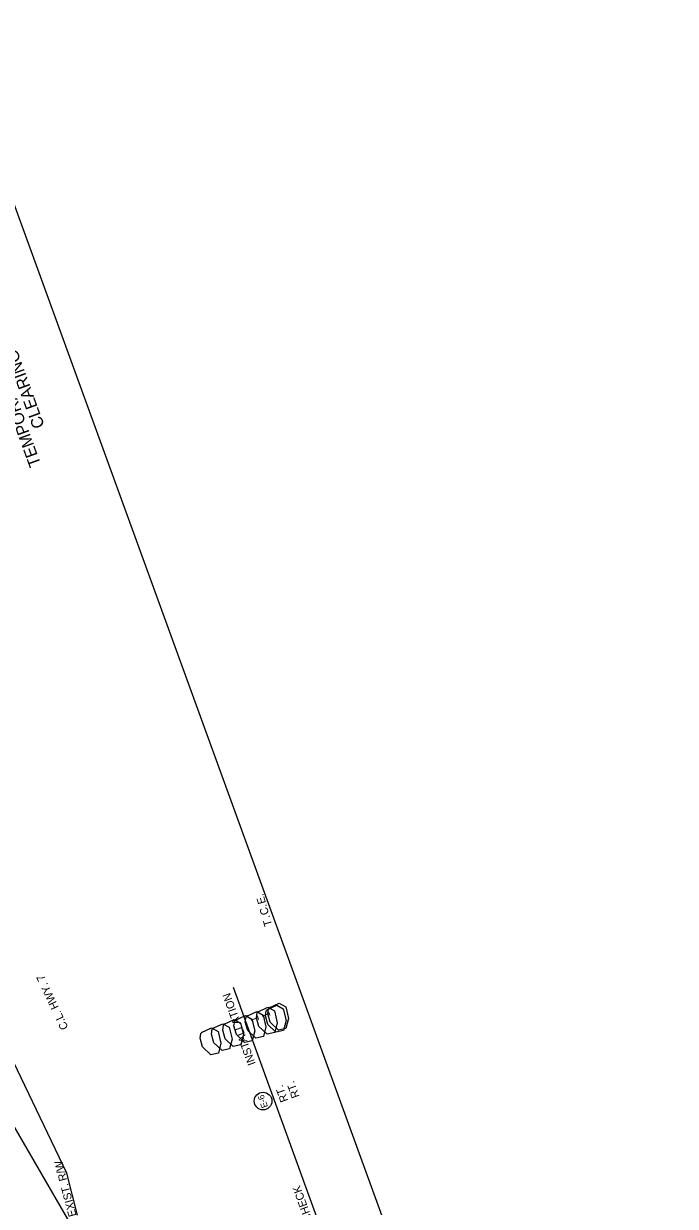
# Model space of a CAD drawing. Extents: x 960650 to 962115, y 1906901 to 1908930.
# Drawn here: x 961626 to 962115, y 1907870 to 1908757 of the extents above; entities that cross this region are included whole.
import ezdxf

# ---------------------------------------------------------------- set-up
doc = ezdxf.new("R2010")
doc.units = 0
for name, color, linetype in [('1', 7, 'Continuous'), ('44', 7, 'Continuous'), ('60', 7, 'Continuous'), ('NO PLOT', 7, 'Continuous'), ('R_Draft', 7, 'Continuous'), ('S_TREE', 7, 'Continuous')]:
    doc.layers.add(name, color=color, linetype=linetype)

msp = doc.modelspace()

# ---------------------------------------------------------------- linework, layer by layer
at = {"layer": '1'}
msp.add_circle((961805.17, 1907948.87), 6.61, dxfattribs=at)
at = {"layer": '44'}
msp.add_line((961865.4, 1907807.44), (961782.97, 1908033.91), dxfattribs=at)
at = {"layer": 'NO PLOT'}
msp.add_lwpolyline([(962114.55, 1907257.7), (961568.91, 1908756.85), (961079.18, 1908578.6), (961182.12, 1908295.76), (961245.55, 1908318.85), (961390.91, 1907919.48), (961327.48, 1907896.39), (961425.36, 1907627.47), (961483.4, 1907648.6), (961600.59, 1907326.6), (961542.56, 1907305.48), (961624.82, 1907079.46)], close=True, dxfattribs=at)
msp.add_lwpolyline([(962114.55, 1907257.7), (961568.91, 1908756.85), (961079.18, 1908578.6), (961182.12, 1908295.76), (961245.55, 1908318.85), (961390.91, 1907919.48), (961327.48, 1907896.39), (961425.36, 1907627.47), (961483.4, 1907648.6), (961600.59, 1907326.6), (961542.56, 1907305.48), (961624.82, 1907079.46)], close=True, dxfattribs=at)
msp.add_lwpolyline([(962114.55, 1907257.7), (961568.91, 1908756.85), (961079.18, 1908578.6), (961182.12, 1908295.76), (961245.55, 1908318.85), (961390.91, 1907919.48), (961327.48, 1907896.39), (961425.36, 1907627.47), (961483.4, 1907648.6), (961600.59, 1907326.6), (961542.56, 1907305.48), (961624.82, 1907079.46)], close=True, dxfattribs=at)
msp.add_lwpolyline([(961666.04, 1907863.2), (961658.05, 1907894.81), (961540.67, 1908139.08), (961533.72, 1908140.56), (961533.72, 1908140.56), (961533.71, 1908140.68), (961532.94, 1908142.63), (961447.22, 1908293.28), (961348.44, 1908423.3), (961301.2, 1908468.29), (961296.15, 1908480.78), (961212.84, 1908631.51), (961200.57, 1908627.76), (961278, 1908455.78), (961347.64, 1908371.59), (961398.93, 1908274.74), (961531.16, 1908140.88), (961533.72, 1908140.56), (961533.72, 1908140.56), (961540.75, 1908123.08), (961535.28, 1908075.65), (961546.11, 1908053.77), (961660.88, 1907856.14)], dxfattribs=at)
at = {"layer": 'S_TREE'}
for points in [[(961801.39, 1908015.72), (961808.86, 1908019.21), (961813.69, 1908016.47), (961815.84, 1908007.64), (961813.9, 1908000.26), (961808.2, 1907998.99), (961802.12, 1908004.87), (961800.26, 1908011.32), (961800.88, 1908014.97), (961802.07, 1908016.2)], [(961801.39, 1908015.72), (961808.86, 1908019.21), (961813.69, 1908016.47), (961815.84, 1908007.64), (961813.9, 1908000.26), (961808.2, 1907998.99), (961802.12, 1908004.87), (961800.26, 1908011.32), (961800.88, 1908014.97), (961802.07, 1908016.2)], [(961808.04, 1908017.22), (961815.51, 1908020.71), (961820.34, 1908017.98), (961822.49, 1908009.15), (961820.55, 1908001.77), (961814.85, 1908000.49), (961808.77, 1908006.38), (961806.91, 1908012.82), (961807.53, 1908016.48), (961808.72, 1908017.7)], [(961809.84, 1908018.8), (961817.32, 1908022.28), (961822.15, 1908019.55), (961824.3, 1908010.72), (961822.36, 1908003.34), (961816.66, 1908002.07), (961810.58, 1908007.95), (961808.72, 1908014.4), (961809.33, 1908018.05), (961810.53, 1908019.27)], [(961776.01, 1908006.48), (961783.49, 1908009.97), (961788.32, 1908007.24), (961790.47, 1907998.41), (961788.53, 1907991.03), (961782.83, 1907989.75), (961776.75, 1907995.64), (961774.89, 1908002.08), (961775.5, 1908005.74), (961776.7, 1908006.96)], [(961776.01, 1908006.48), (961783.49, 1908009.97), (961788.32, 1908007.24), (961790.47, 1907998.41), (961788.53, 1907991.03), (961782.83, 1907989.75), (961776.75, 1907995.64), (961774.89, 1908002.08), (961775.5, 1908005.74), (961776.7, 1908006.96)], [(961776.01, 1908006.48), (961783.49, 1908009.97), (961788.32, 1908007.24), (961790.47, 1907998.41), (961788.53, 1907991.03), (961782.83, 1907989.75), (961776.75, 1907995.64), (961774.89, 1908002.08), (961775.5, 1908005.74), (961776.7, 1908006.96)], [(961776.01, 1908006.48), (961783.49, 1908009.97), (961788.32, 1908007.24), (961790.47, 1907998.41), (961788.53, 1907991.03), (961782.83, 1907989.75), (961776.75, 1907995.64), (961774.89, 1908002.08), (961775.5, 1908005.74), (961776.7, 1908006.96)], [(961776.01, 1908006.48), (961783.49, 1908009.97), (961788.32, 1908007.24), (961790.47, 1907998.41), (961788.53, 1907991.03), (961782.83, 1907989.75), (961776.75, 1907995.64), (961774.89, 1908002.08), (961775.5, 1908005.74), (961776.7, 1908006.96)], [(961784.47, 1908009.56), (961791.95, 1908013.05), (961796.77, 1908010.32), (961798.92, 1908001.49), (961796.99, 1907994.11), (961791.29, 1907992.83), (961785.21, 1907998.72), (961783.35, 1908005.16), (961783.96, 1908008.82), (961785.15, 1908010.04)], [(961784.47, 1908009.56), (961791.95, 1908013.05), (961796.77, 1908010.32), (961798.92, 1908001.49), (961796.99, 1907994.11), (961791.29, 1907992.83), (961785.21, 1907998.72), (961783.35, 1908005.16), (961783.96, 1908008.82), (961785.15, 1908010.04)], [(961784.47, 1908009.56), (961791.95, 1908013.05), (961796.77, 1908010.32), (961798.92, 1908001.49), (961796.99, 1907994.11), (961791.29, 1907992.83), (961785.21, 1907998.72), (961783.35, 1908005.16), (961783.96, 1908008.82), (961785.15, 1908010.04)], [(961784.47, 1908009.56), (961791.95, 1908013.05), (961796.77, 1908010.32), (961798.92, 1908001.49), (961796.99, 1907994.11), (961791.29, 1907992.83), (961785.21, 1907998.72), (961783.35, 1908005.16), (961783.96, 1908008.82), (961785.15, 1908010.04)], [(961784.47, 1908009.56), (961791.95, 1908013.05), (961796.77, 1908010.32), (961798.92, 1908001.49), (961796.99, 1907994.11), (961791.29, 1907992.83), (961785.21, 1907998.72), (961783.35, 1908005.16), (961783.96, 1908008.82), (961785.15, 1908010.04)], [(961792.93, 1908012.64), (961800.4, 1908016.13), (961805.23, 1908013.39), (961807.38, 1908004.57), (961805.45, 1907997.18), (961799.74, 1907995.91), (961793.66, 1908001.8), (961791.81, 1908008.24), (961792.42, 1908011.9), (961793.61, 1908013.12)], [(961759.1, 1908000.33), (961766.57, 1908003.81), (961771.4, 1908001.08), (961773.55, 1907992.25), (961771.62, 1907984.87), (961765.91, 1907983.6), (961759.83, 1907989.48), (961757.98, 1907995.93), (961758.59, 1907999.58), (961759.78, 1908000.8)], [(961767.56, 1908003.41), (961775.03, 1908006.89), (961779.86, 1908004.16), (961782.01, 1907995.33), (961780.07, 1907987.95), (961774.37, 1907986.68), (961768.29, 1907992.56), (961766.43, 1907999.01), (961767.05, 1908002.66), (961768.24, 1908003.88)], [(961767.56, 1908003.41), (961775.03, 1908006.89), (961779.86, 1908004.16), (961782.01, 1907995.33), (961780.07, 1907987.95), (961774.37, 1907986.68), (961768.29, 1907992.56), (961766.43, 1907999.01), (961767.05, 1908002.66), (961768.24, 1908003.88)], [(961767.56, 1908003.41), (961775.03, 1908006.89), (961779.86, 1908004.16), (961782.01, 1907995.33), (961780.07, 1907987.95), (961774.37, 1907986.68), (961768.29, 1907992.56), (961766.43, 1907999.01), (961767.05, 1908002.66), (961768.24, 1908003.88)]]:
    msp.add_lwpolyline(points, dxfattribs=at)

# ---------------------------------------------------------------- texts
at = {"layer": '1'}
msp.add_text('E-6 ', height=4.8, rotation=110, dxfattribs=at).set_placement((961808.91, 1907944.7))
at = {"layer": '44'}
for s, p in [('INSTALLATION', (961799.74, 1907976.85)), ('1', (961802.5, 1908009.3)), ('1', (961810.96, 1908012.38)), ('RT.', (961824.18, 1907949.26)), ('RT.', (961832.64, 1907952.34)), ('ROCK DITCH CHECK', (961860.23, 1907810.66))]:
    msp.add_text(s, height=6, rotation=110, dxfattribs=at).set_placement(p)
at = {"layer": '60'}
for s, p in [('TEMPORARY EROSION CONTROL DETAILS', (961638.71, 1908426.37)), ('CLEARING AND GRUBBING STAGE', (961641.4, 1908455.18))]:
    msp.add_text(s, height=9, rotation=110, dxfattribs=at).set_placement(p)
at = {"layer": 'R_Draft'}
for s, rotation, p in [('E', 105.85702, (961807.38, 1908097.54)), ('.', 105.85702, (961805.9, 1908102.72)), ('C', 105.85702, (961809.73, 1908089.27)), ('.', 105.85702, (961808.18, 1908094.73)), ('T', 105.85702, (961812.13, 1908080.82)), ('.', 105.85702, (961810.53, 1908086.45)), ('C.L. HWY. 7', 115.13979, (961659.2, 1908003.88)), ('EXIST. R/W', 104.76842, (961665.25, 1907862.97))]:
    msp.add_text(s, height=6, rotation=rotation, dxfattribs=at).set_placement(p)

doc.saveas('drawing.dxf')
